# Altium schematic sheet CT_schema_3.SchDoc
size 282 x 169 mm
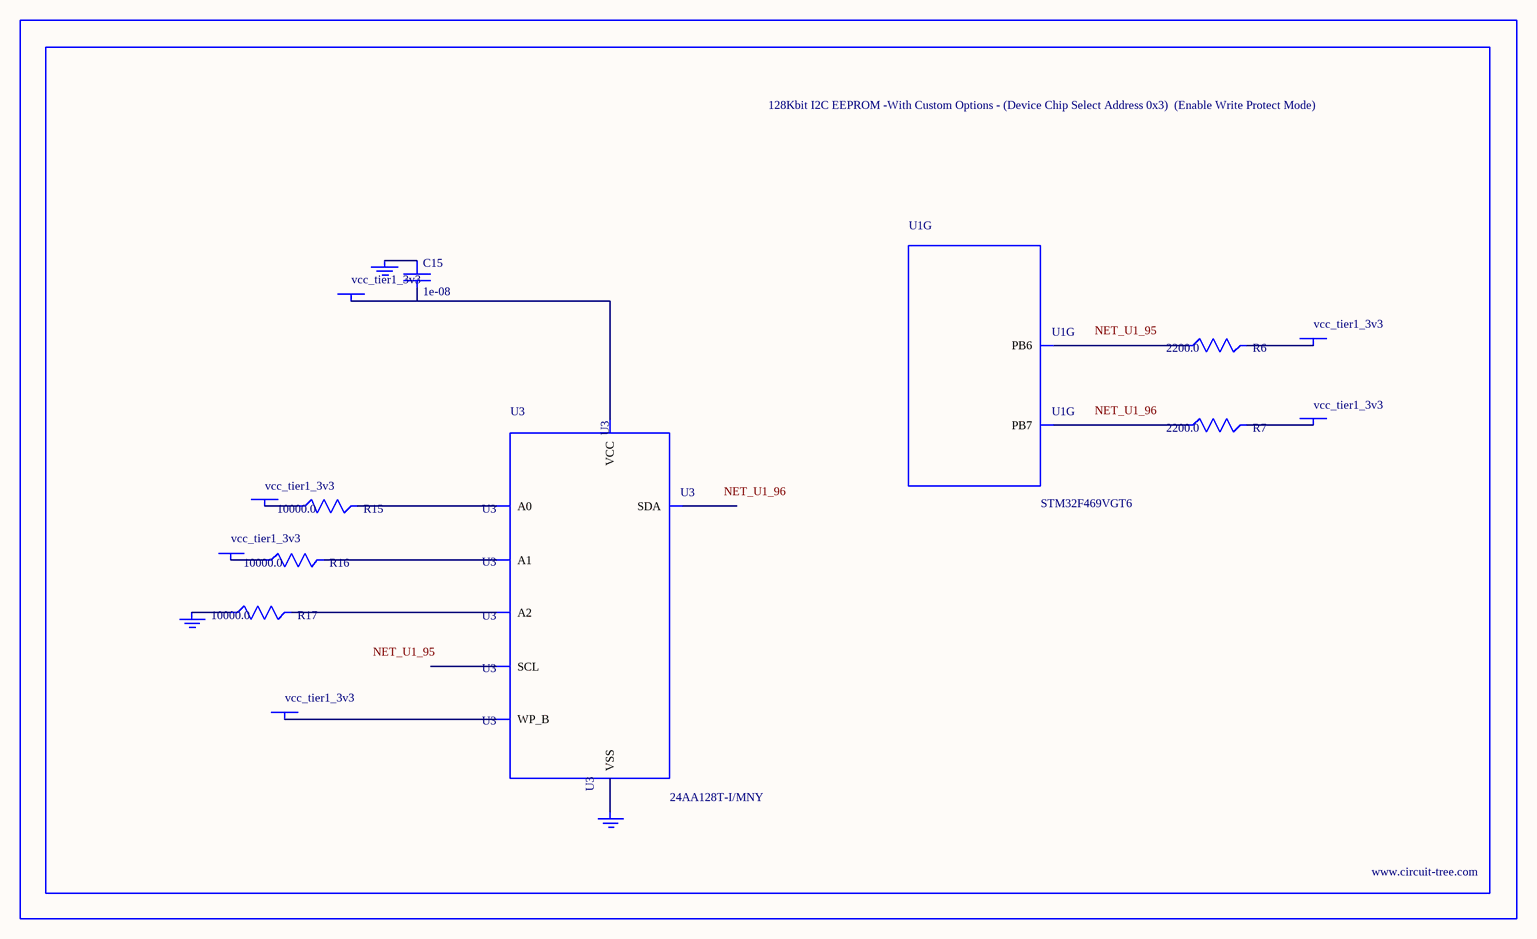
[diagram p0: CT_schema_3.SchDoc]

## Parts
BORDER2  (no value)
C15  1e-08  [C0402]
GND_INSTANCE_2_0  (no value)
GND_INSTANCE_2_1  (no value)
GND_INSTANCE_2_2  (no value)
POWER_INSTANCE_2_0  vcc_tier1_3v3
POWER_INSTANCE_2_1  vcc_tier1_3v3
POWER_INSTANCE_2_2  vcc_tier1_3v3
POWER_INSTANCE_2_3  vcc_tier1_3v3
POWER_INSTANCE_2_4  vcc_tier1_3v3
POWER_INSTANCE_2_5  vcc_tier1_3v3
R6  2200.0  [R0603]
R7  2200.0  [R0603]
R15  10000.0  [R0603]
R16  10000.0  [R0603]
R17  10000.0  [R0603]
U1  STM32F469VGT6  [LQFP100]  (part G of 10)
U3  24AA128T-I/MNY  [TDFN-8/6MM]

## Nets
NetC15_1: C15.1 GND_INSTANCE_2_1.0(GND)
NetC15_2: C15.2 POWER_INSTANCE_2_3.0(PWR) U3.8(VCC)
NetGND_INSTANCE_2_0_0: GND_INSTANCE_2_0.0(GND) R17.1
NetGND_INSTANCE_2_2_0: GND_INSTANCE_2_2.0(GND) U3.4(VSS)
NetPOWER_INSTANCE_2_0_0: POWER_INSTANCE_2_0.0(PWR) R15.1
NetPOWER_INSTANCE_2_1_0: POWER_INSTANCE_2_1.0(PWR) R16.1
NetPOWER_INSTANCE_2_2_0: POWER_INSTANCE_2_2.0(PWR) U3.7(WP_B)
NetPOWER_INSTANCE_2_4_0: POWER_INSTANCE_2_4.0(PWR) R6.2
NetPOWER_INSTANCE_2_5_0: POWER_INSTANCE_2_5.0(PWR) R7.2
NetR6_1: R6.1 U1.95(PB6)
NetR7_1: R7.1 U1.96(PB7)
NetR15_2: R15.2 U3.1(A0)
NetR16_2: R16.2 U3.2(A1)
NetR17_2: R17.2 U3.3(A2)

Not connected (* = marked no-connect by the designer): U3 5(SDA) 6(SCL)

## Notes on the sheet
- Labels drawn without touching a wire or pin: NET_U1_95, NET_U1_96

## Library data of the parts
BORDER2 = BORDER_PAGE2
C15 = C0402C103K3RAC
GND_INSTANCE_2_0-GND_INSTANCE_2_2 = GND
POWER_INSTANCE_2_0-POWER_INSTANCE_2_5 = PWR
R6 R7 = RC0603JR-072K2L
R15-R17 = RC0603JR-0710KL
